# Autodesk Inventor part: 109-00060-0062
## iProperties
Shininess: 64.0
Length Units: 11272
Angle Units: 11279
Time Units: 11290
Mass Units: 11286
Length Display Precision: 3
Angle Display Precision: 2
Compacted: True
Part Number: 109-00060-0062
Document SubType Name: Modeling
Created: 2004-01
Designer: John Muchow
Manufacturer: Standard
Standards Organization: Custom
Material: STEEL, AUSTENTIC STAINLESS
Description: COTTERS, HAIRPIN
Engr Approved By: John M
Density: 0.0
Volumn: 0.0
Area: 0.0
PropertySet Name: Model Information
Control State: 0
Master: False
Checked Out: False
Author: John Muchow
Revision Number: A
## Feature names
1. Sweep1
